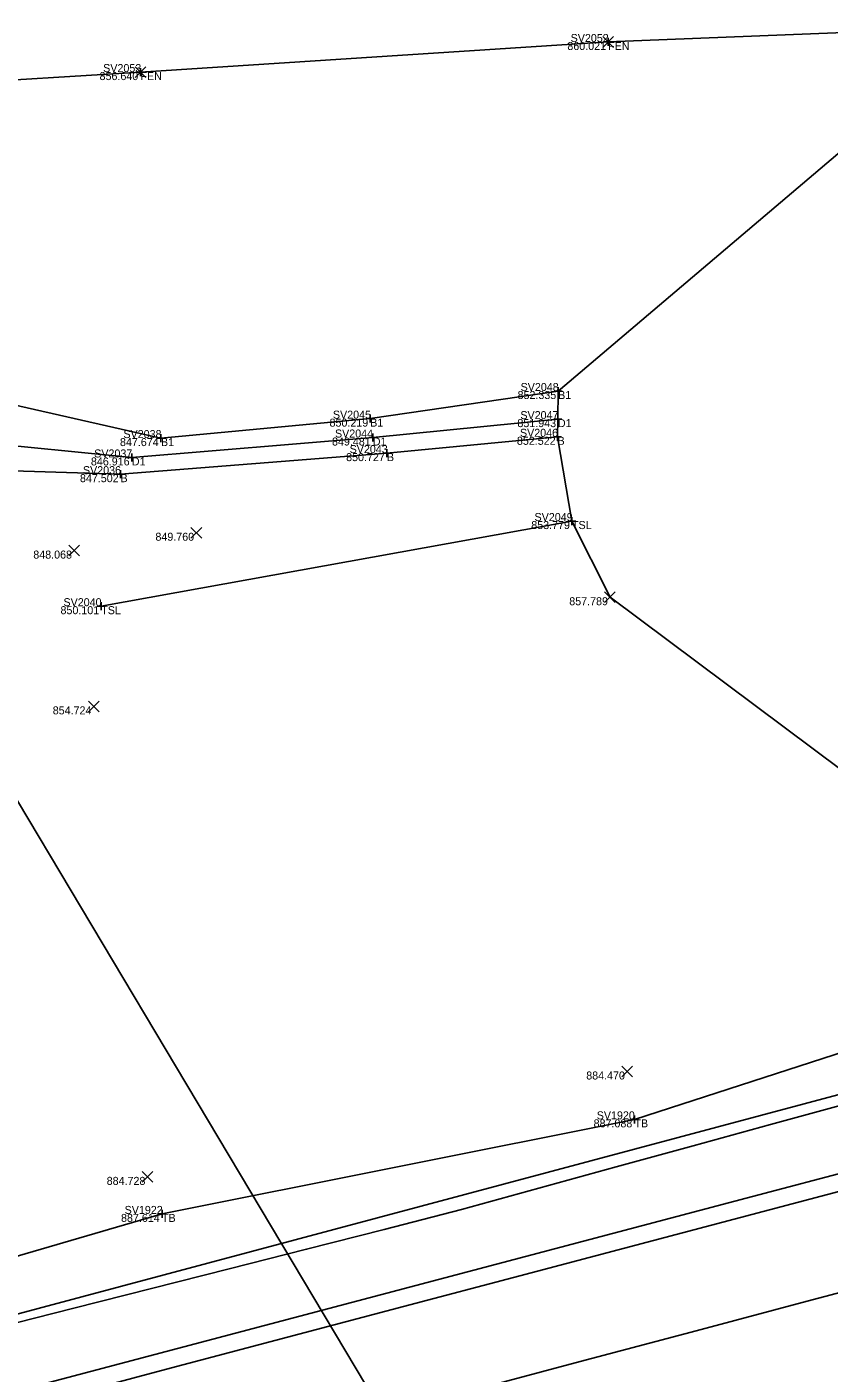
# Model space of a CAD drawing. Extents: x 2125299 to 2129212, y 713100 to 714300.
# Drawn here: x 2127564.8 to 2127665, y 713899.3 to 714067.5 of the extents above; entities that cross this region are included whole.
import ezdxf

# ---------------------------------------------------------------- set-up
doc = ezdxf.new("R2010")
doc.units = 0
for name, color, linetype in [('_CIVIL_CONSTRUCTION', 7, 'Continuous'), ('DR_X_Ditch', 7, 'Continuous'), ('DR_X_Storm_Sewer', 7, 'Continuous'), ('DT_X_Terrain_Boundary', 7, 'Continuous'), ('PV_X_EOP', 7, 'Continuous'), ('PV_X_Shoulder_Rumble_Strip', 7, 'Continuous'), ('RD_X_Fence', 7, 'Continuous'), ('RW_P_Esmt_TMP', 7, 'Continuous'), ('RW_X_Esmt_CH', 7, 'Continuous'), ('RW_X_Fee_WL', 7, 'Continuous'), ('SC_Scratch1', 7, 'Continuous'), ('SC_Scratch2', 7, 'Continuous'), ('SV_X_Break_Lines', 7, 'Continuous'), ('SV_X_Mon_Cells_Found', 7, 'Continuous'), ('SV_X_Text_Elevation', 7, 'Continuous'), ('SV_X_Toe_of_Slope', 7, 'Continuous'), ('SV_X_Top_of_Bank', 7, 'Continuous')]:
    doc.layers.add(name, color=color, linetype=linetype)

msp = doc.modelspace()

# ---------------------------------------------------------------- linework, layer by layer
at = {"layer": '_CIVIL_CONSTRUCTION'}
msp.add_lwpolyline([(2127372.97, 713831.37), (2127387.47, 713835.22), (2127401.97, 713839.08), (2127416.46, 713842.93), (2127430.96, 713846.79), (2127445.46, 713850.64), (2127459.95, 713854.5), (2127474.45, 713858.35), (2127488.94, 713862.21), (2127503.44, 713866.06), (2127517.94, 713869.92), (2127532.43, 713873.77), (2127546.93, 713877.63), (2127561.42, 713881.48), (2127575.92, 713885.34), (2127590.42, 713889.19), (2127604.91, 713893.05), (2127619.41, 713896.9), (2127633.91, 713900.76), (2127648.4, 713904.61), (2127662.9, 713908.47), (2127677.41, 713912.28)], dxfattribs=at)
at = {"layer": 'DR_X_Ditch'}
msp.add_lwpolyline([(2127540.13, 714011.53), (2127546.49, 714011.47), (2127551.01, 714016.41), (2127577.89, 714013.74), (2127607.99, 714016.23), (2127631.12, 714018.53)], dxfattribs=at)
at = {"layer": 'DR_X_Storm_Sewer'}
msp.add_line((2127551.46, 713991.15), (2127754.53, 713650.69), dxfattribs=at)
at = {"layer": 'DT_X_Terrain_Boundary'}
msp.add_lwpolyline([(2127695.62, 713952.95), (2127637.63, 713996.27), (2127632.88, 714005.79), (2127631.08, 714016.32), (2127631.12, 714018.53), (2127631.15, 714022.04), (2127684.79, 714067.54), (2127637.39, 714065.66), (2127578.97, 714061.9), (2127530.03, 714058.91), (2127501.39, 714057.24), (2127432.97, 714052.74), (2127408.21, 714050.18), (2127386.8, 714040.45), (2127393.47, 714022.12), (2127395.48, 714001.81), (2127396.17, 713987.66), (2127393.88, 713985.04), (2127395.42, 713982.63), (2127376.91, 713954.19)], dxfattribs=at)
at = {"layer": 'PV_X_EOP'}
msp.add_lwpolyline([(2127532, 713897.08), (2127541.65, 713899.7), (2127551.3, 713902.32), (2127560.95, 713904.95), (2127570.65, 713907.41), (2127580.34, 713909.86), (2127590.03, 713912.32), (2127599.73, 713914.78), (2127609.42, 713917.24), (2127619.09, 713919.77), (2127628.73, 713922.42), (2127638.38, 713925.07), (2127648.02, 713927.72), (2127657.66, 713930.36), (2127667.31, 713933.01)], dxfattribs=at)
at = {"layer": 'PV_X_Shoulder_Rumble_Strip'}
msp.add_lwpolyline([(2127379.28, 713847.95), (2127393.77, 713851.83), (2127408.26, 713855.7), (2127422.75, 713859.58), (2127437.24, 713863.45), (2127451.73, 713867.33), (2127466.21, 713871.2), (2127480.7, 713875.08), (2127495.19, 713878.95), (2127509.68, 713882.82), (2127524.17, 713886.66), (2127538.67, 713890.5), (2127553.17, 713894.33), (2127567.67, 713898.17), (2127582.17, 713902), (2127596.67, 713905.84), (2127611.16, 713909.67), (2127625.66, 713913.5), (2127640.16, 713917.34), (2127654.66, 713921.17), (2127669.16, 713925.01)], dxfattribs=at)
at = {"layer": 'RD_X_Fence'}
msp.add_lwpolyline([(2127684.79, 714067.54), (2127637.39, 714065.66), (2127578.97, 714061.9), (2127530.03, 714058.91), (2127501.39, 714057.24), (2127432.97, 714052.74), (2127408.21, 714050.18), (2127386.8, 714040.45)], dxfattribs=at)
at = {"layer": 'SC_Scratch1'}
msp.add_lwpolyline([(2127987.17, 714018.86), (2127920.93, 714001.38), (2127683.07, 713938.63), (2127539.5, 713900.27), (2127439.69, 713873.74), (2127381.79, 713858.41), (2127328.47, 713844.31), (2127152.7, 713796.25), (2127072.88, 713773.07)], dxfattribs=at)
at = {"layer": 'SC_Scratch2'}
msp.add_lwpolyline([(2127379.92, 713845.89), (2127394.41, 713849.77), (2127408.9, 713853.64), (2127423.39, 713857.52), (2127437.89, 713861.39), (2127452.38, 713865.27), (2127466.87, 713869.14), (2127481.36, 713873.02), (2127495.85, 713876.89), (2127510.34, 713880.77), (2127524.84, 713884.61), (2127539.34, 713888.44), (2127553.84, 713892.28), (2127568.34, 713896.11), (2127582.85, 713899.95), (2127597.35, 713903.79), (2127611.85, 713907.62), (2127626.35, 713911.46), (2127640.85, 713915.29), (2127655.35, 713919.13), (2127669.85, 713922.96)], dxfattribs=at)
at = {"layer": 'SV_X_Break_Lines'}
for points in [[(2127396.17, 713987.66), (2127436.26, 713998.39), (2127464.75, 714000.17), (2127475.3, 714002.88), (2127478.27, 714012.29), (2127496.65, 714014.57), (2127503.83, 714014), (2127524.18, 714018.5), (2127537.3, 714018.52), (2127543.02, 714017.95), (2127558.9, 714021.26), (2127581.53, 714016.16), (2127607.67, 714018.59), (2127631.15, 714022.04)], [(2127395.42, 713982.63), (2127429.29, 713991.11), (2127443.13, 713988.6), (2127450.21, 713993.91), (2127464.45, 713992.26), (2127481.7, 713997.56), (2127482.21, 714004.47), (2127504.31, 714008.03), (2127525.23, 714009.25), (2127535.9, 714006.53), (2127544.89, 713989.22), (2127538.94, 713987.02), (2127539.69, 713985.54), (2127549.34, 713988.97), (2127555.25, 713991.9), (2127560.41, 713995.32), (2127559.81, 713996.35), (2127556.78, 713996.1), (2127549.83, 714010.41), (2127558.95, 714012.21), (2127576.48, 714011.65), (2127609.76, 714014.28), (2127631.08, 714016.32)]]:
    msp.add_lwpolyline(points, dxfattribs=at)
at = {"layer": 'SV_X_Mon_Cells_Found'}
for p, q in [((2127636.89, 714065.66), (2127637.89, 714065.66)), ((2127637.39, 714066.16), (2127637.39, 714065.16)), ((2127637.39, 714065.66), (2127637.39, 714065.66)), ((2127578.97, 714062.4), (2127578.97, 714061.4)), ((2127578.47, 714061.9), (2127579.47, 714061.9)), ((2127578.97, 714061.9), (2127578.97, 714061.9)), ((2127630.65, 714022.04), (2127631.65, 714022.04)), ((2127631.15, 714022.54), (2127631.15, 714021.54)), ((2127631.15, 714022.04), (2127631.15, 714022.04)), ((2127607.17, 714018.59), (2127608.17, 714018.59)), ((2127607.67, 714019.09), (2127607.67, 714018.09)), ((2127607.67, 714018.59), (2127607.67, 714018.59)), ((2127631.12, 714019.03), (2127631.12, 714018.03)), ((2127630.62, 714018.53), (2127631.62, 714018.53)), ((2127631.12, 714018.53), (2127631.12, 714018.53)), ((2127581.03, 714016.16), (2127582.03, 714016.16)), ((2127581.53, 714016.66), (2127581.53, 714015.66)), ((2127581.53, 714016.16), (2127581.53, 714016.16)), ((2127607.49, 714016.23), (2127608.49, 714016.23)), ((2127607.99, 714016.73), (2127607.99, 714015.73)), ((2127607.99, 714016.23), (2127607.99, 714016.23)), ((2127630.58, 714016.32), (2127631.58, 714016.32)), ((2127631.08, 714016.82), (2127631.08, 714015.82)), ((2127631.08, 714016.32), (2127631.08, 714016.32)), ((2127577.39, 714013.74), (2127578.39, 714013.74)), ((2127577.89, 714014.24), (2127577.89, 714013.24)), ((2127577.89, 714013.74), (2127577.89, 714013.74)), ((2127609.26, 714014.28), (2127610.26, 714014.28)), ((2127609.76, 714014.78), (2127609.76, 714013.78)), ((2127609.76, 714014.28), (2127609.76, 714014.28)), ((2127576.48, 714012.15), (2127576.48, 714011.15)), ((2127575.98, 714011.65), (2127576.98, 714011.65)), ((2127576.48, 714011.65), (2127576.48, 714011.65)), ((2127632.38, 714005.79), (2127633.38, 714005.79)), ((2127632.88, 714006.29), (2127632.88, 714005.29)), ((2127632.88, 714005.79), (2127632.88, 714005.79)), ((2127573.57, 713995.15), (2127574.57, 713995.15)), ((2127574.07, 713995.65), (2127574.07, 713994.65)), ((2127574.07, 713995.15), (2127574.07, 713995.15)), ((2127640.68, 713931.52), (2127640.68, 713930.52)), ((2127640.18, 713931.02), (2127641.18, 713931.02)), ((2127640.68, 713931.02), (2127640.68, 713931.02)), ((2127581.66, 713919.7), (2127581.66, 713918.7)), ((2127581.16, 713919.2), (2127582.16, 713919.2)), ((2127581.66, 713919.2), (2127581.66, 713919.2))]:
    msp.add_line(p, q, dxfattribs=at)
at = {"layer": 'SV_X_Text_Elevation'}
for p, q in [((2127636.72, 714064.99), (2127638.05, 714066.33)), ((2127636.72, 714066.33), (2127638.05, 714064.99)), ((2127578.31, 714061.24), (2127579.64, 714062.57)), ((2127578.31, 714062.57), (2127579.64, 714061.24)), ((2127585.28, 714003.66), (2127586.62, 714005)), ((2127585.28, 714005), (2127586.62, 714003.66)), ((2127570.02, 714001.43), (2127571.35, 714002.76)), ((2127570.02, 714002.76), (2127571.35, 714001.43)), ((2127636.96, 713995.6), (2127638.29, 713996.93)), ((2127636.96, 713996.93), (2127638.29, 713995.6)), ((2127572.46, 713981.96), (2127573.8, 713983.3)), ((2127572.46, 713983.3), (2127573.8, 713981.96)), ((2127639.1, 713936.34), (2127640.44, 713937.67)), ((2127639.1, 713937.67), (2127640.44, 713936.34)), ((2127579.19, 713923.16), (2127580.52, 713924.49)), ((2127579.19, 713924.49), (2127580.52, 713923.16))]:
    msp.add_line(p, q, dxfattribs=at)
at = {"layer": 'SV_X_Toe_of_Slope'}
msp.add_lwpolyline([(2127574.07, 713995.15), (2127632.88, 714005.79)], dxfattribs=at)
at = {"layer": 'SV_X_Top_of_Bank'}
msp.add_lwpolyline([(2127757.05, 713965.16), (2127696.6, 713949.14), (2127640.68, 713931.02), (2127581.66, 713919.2), (2127522.16, 713901.86), (2127455.22, 713885.36), (2127396.67, 713869.65)], dxfattribs=at)

# ---------------------------------------------------------------- texts
at = {"layer": 'RW_P_Esmt_TMP'}
for s, p in [('FEN', (2127637.39, 714064.66)), ('FEN', (2127578.97, 714060.9)), ('B1', (2127631.15, 714021.04)), ('B1', (2127607.67, 714017.59)), ('D1', (2127631.12, 714017.53)), ('B1', (2127581.53, 714015.16)), ('D1', (2127607.99, 714015.23)), ('B', (2127631.08, 714015.32)), ('D1', (2127577.89, 714012.74)), ('B', (2127609.76, 714013.28)), ('B', (2127576.48, 714010.65)), ('TSL', (2127632.88, 714004.79)), ('TSL', (2127574.07, 713994.15)), ('TB', (2127640.68, 713930.02)), ('TB', (2127581.66, 713918.2))]:
    msp.add_text(s, height=1, dxfattribs=at).set_placement(p)
at = {"layer": 'RW_X_Esmt_CH'}
for s, p in [('SV2052', (2127632.71, 714065.66)), ('SV2053', (2127574.31, 714061.9)), ('SV2048', (2127626.46, 714022.04)), ('SV2045', (2127603.01, 714018.59)), ('SV2047', (2127626.43, 714018.53)), ('SV2038', (2127576.84, 714016.16)), ('SV2044', (2127603.27, 714016.23)), ('SV2046', (2127626.38, 714016.32)), ('SV2043', (2127605.1, 714014.28)), ('SV2037', (2127573.19, 714013.74)), ('SV2036', (2127571.78, 714011.65)), ('SV2049', (2127628.2, 714005.79)), ('SV2040', (2127569.35, 713995.15)), ('SV1920', (2127635.97, 713931.02)), ('SV1922', (2127576.99, 713919.2))]:
    msp.add_text(s, height=1, dxfattribs=at).set_placement(p)
at = {"layer": 'RW_X_Fee_WL'}
for s, p in [('860.021', (2127632.3, 714064.66)), ('860.021', (2127632.3, 714064.66)), ('856.640', (2127573.86, 714060.9)), ('856.640', (2127573.86, 714060.9)), ('852.335', (2127626.08, 714021.04)), ('850.219', (2127602.59, 714017.59)), ('851.943', (2127626.06, 714017.53)), ('847.674', (2127576.41, 714015.16)), ('849.481', (2127602.9, 714015.23)), ('852.522', (2127626, 714015.32)), ('846.916', (2127572.78, 714012.74)), ('850.727', (2127604.66, 714013.28)), ('847.502', (2127571.41, 714010.65)), ('853.779', (2127627.79, 714004.79)), ('849.760', (2127580.84, 714003.33)), ('848.068', (2127565.58, 714001.1)), ('850.101', (2127568.98, 713994.15)), ('857.789', (2127632.54, 713995.27)), ('854.724', (2127568.01, 713981.63)), ('884.470', (2127634.66, 713936)), ('887.088', (2127635.58, 713930.02)), ('884.728', (2127574.75, 713922.83)), ('887.614', (2127576.54, 713918.2))]:
    msp.add_text(s, height=1, dxfattribs=at).set_placement(p)

doc.saveas('drawing.dxf')
